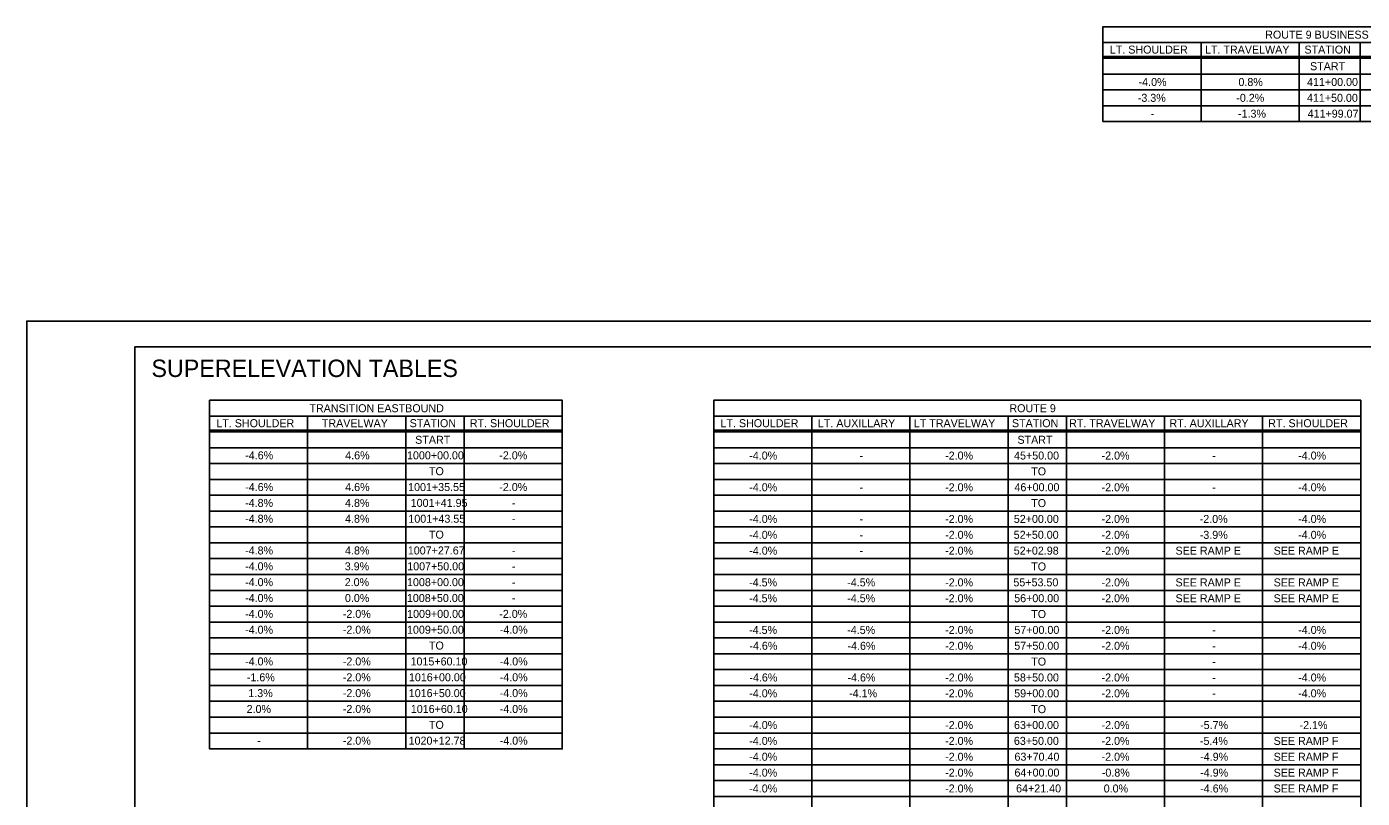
# Model space of a CAD drawing. Extents: x -15319374 to 1762012, y 465773 to 3693661.
# Drawn here: x -15317328 to -15316827, y 3691684 to 3691973 of the extents above; entities that cross this region are included whole.
import ezdxf

# ---------------------------------------------------------------- set-up
doc = ezdxf.new("R2010")
doc.units = 0
for name, color, linetype in [('BORDER', 7, 'Continuous'), ('DIMENSIONS', 7, 'Continuous'), ('PLOT BOUNDARY', 7, 'Continuous')]:
    doc.layers.add(name, color=color, linetype=linetype)

msp = doc.modelspace()

# ---------------------------------------------------------------- linework, layer by layer
at = {"layer": 'BORDER'}
for p, q in [((-15316887.84, 3691967.13), (-15316887.84, 3691937.48)), ((-15316851.07, 3691967.13), (-15316851.07, 3691937.48)), ((-15316828.2, 3691967.13), (-15316828.2, 3691937.48)), ((-15316924.61, 3691961.85), (-15316755.66, 3691961.85)), ((-15316924.61, 3691961.25), (-15316755.66, 3691961.25)), ((-15316924.61, 3691955.31), (-15316755.66, 3691955.31)), ((-15316924.61, 3691955.31), (-15316755.66, 3691955.31)), ((-15316924.61, 3691955.31), (-15316755.66, 3691955.31)), ((-15316924.61, 3691949.37), (-15316755.66, 3691949.37)), ((-15316924.61, 3691943.42), (-15316755.66, 3691943.42)), ((-15317259.46, 3691827.08), (-15317259.46, 3691708.88)), ((-15317222.69, 3691827.08), (-15317222.69, 3691702.35)), ((-15317185.92, 3691827.08), (-15317185.92, 3691702.35)), ((-15317164.05, 3691827.08), (-15317164.05, 3691702.35)), ((-15317070.51, 3691827.08), (-15317070.51, 3691482.47)), ((-15317033.74, 3691827.08), (-15317033.74, 3691482.47)), ((-15316996.97, 3691827.08), (-15316996.97, 3691482.47)), ((-15316960.21, 3691827.08), (-15316960.21, 3691482.47)), ((-15316938.33, 3691827.08), (-15316938.33, 3691482.47)), ((-15316901.56, 3691827.08), (-15316901.56, 3691482.47)), ((-15316864.8, 3691827.08), (-15316864.8, 3691482.47)), ((-15316828.03, 3691827.08), (-15316828.03, 3691482.47)), ((-15317259.46, 3691821.8), (-15317127.28, 3691821.8)), ((-15317259.46, 3691821.2), (-15317127.28, 3691821.2)), ((-15317033.74, 3691821.8), (-15317070.51, 3691821.8)), ((-15317033.74, 3691821.2), (-15317070.51, 3691821.2)), ((-15317070.51, 3691821.2), (-15317070.51, 3691482.47)), ((-15317033.74, 3691821.8), (-15316828.03, 3691821.8)), ((-15317033.74, 3691821.2), (-15316828.03, 3691821.2)), ((-15317259.46, 3691815.26), (-15317127.28, 3691815.26)), ((-15317259.46, 3691815.26), (-15317127.28, 3691815.26)), ((-15317259.46, 3691815.26), (-15317127.28, 3691815.26)), ((-15317070.51, 3691815.26), (-15316828.03, 3691815.26)), ((-15317070.51, 3691815.26), (-15316828.03, 3691815.26)), ((-15317070.51, 3691815.26), (-15316828.03, 3691815.26)), ((-15317259.46, 3691809.32), (-15317127.28, 3691809.32)), ((-15317070.51, 3691809.32), (-15316828.03, 3691809.32)), ((-15317259.46, 3691803.38), (-15317127.28, 3691803.38)), ((-15317070.51, 3691803.38), (-15316828.03, 3691803.38)), ((-15317259.46, 3691797.43), (-15317127.28, 3691797.43)), ((-15317070.51, 3691797.43), (-15316828.03, 3691797.43)), ((-15317259.46, 3691791.49), (-15317127.28, 3691791.49)), ((-15317070.51, 3691791.49), (-15316828.03, 3691791.49)), ((-15317259.46, 3691785.55), (-15317127.28, 3691785.55)), ((-15317070.51, 3691785.55), (-15316828.03, 3691785.55)), ((-15317259.46, 3691779.61), (-15317127.28, 3691779.61)), ((-15317070.51, 3691779.61), (-15316828.03, 3691779.61)), ((-15317259.46, 3691773.66), (-15317127.28, 3691773.66)), ((-15317070.51, 3691773.66), (-15316828.03, 3691773.66)), ((-15317259.46, 3691767.72), (-15317127.28, 3691767.72)), ((-15317070.51, 3691767.72), (-15316828.03, 3691767.72)), ((-15317259.46, 3691761.78), (-15317127.28, 3691761.78)), ((-15317070.51, 3691761.78), (-15316828.03, 3691761.78)), ((-15317259.46, 3691755.83), (-15317127.28, 3691755.83)), ((-15317070.51, 3691755.83), (-15316828.03, 3691755.83)), ((-15317259.46, 3691749.89), (-15317127.28, 3691749.89)), ((-15317070.51, 3691749.89), (-15316828.03, 3691749.89)), ((-15317259.46, 3691743.95), (-15317127.28, 3691743.95)), ((-15317070.51, 3691743.95), (-15316828.03, 3691743.95)), ((-15317259.46, 3691738.01), (-15317127.28, 3691738.01)), ((-15317070.51, 3691738.01), (-15316828.03, 3691738.01)), ((-15317259.46, 3691732.06), (-15317127.28, 3691732.06)), ((-15317070.51, 3691732.06), (-15316828.03, 3691732.06)), ((-15317259.46, 3691726.12), (-15317127.28, 3691726.12)), ((-15317070.51, 3691726.12), (-15316828.03, 3691726.12)), ((-15317259.46, 3691720.18), (-15317127.28, 3691720.18)), ((-15317070.51, 3691720.18), (-15316828.03, 3691720.18)), ((-15317259.46, 3691714.24), (-15317127.28, 3691714.24)), ((-15317070.51, 3691714.24), (-15316828.03, 3691714.24)), ((-15317259.46, 3691708.29), (-15317127.28, 3691708.29)), ((-15317070.51, 3691708.29), (-15316828.03, 3691708.29)), ((-15317259.46, 3691702.35), (-15317127.28, 3691702.35)), ((-15317070.51, 3691702.35), (-15316828.03, 3691702.35)), ((-15317070.51, 3691696.41), (-15316828.03, 3691696.41)), ((-15317070.51, 3691690.46), (-15316828.03, 3691690.46)), ((-15317070.51, 3691684.52), (-15316828.03, 3691684.52))]:
    msp.add_line(p, q, dxfattribs=at)
for points in [[(-15316924.61, 3691967.13), (-15316924.61, 3691973.07), (-15316755.66, 3691973.07), (-15316755.66, 3691967.13)], [(-15317259.46, 3691827.08), (-15317259.46, 3691833.02), (-15317127.28, 3691833.02), (-15317127.28, 3691827.08)], [(-15317033.74, 3691833.02), (-15317070.51, 3691833.02), (-15317070.51, 3691827.08)], [(-15317033.74, 3691833.02), (-15316864.8, 3691833.02)], [(-15316864.8, 3691833.02), (-15316828.03, 3691833.02), (-15316828.03, 3691827.08)]]:
    msp.add_lwpolyline(points, dxfattribs=at)
for points in [[(-15316924.61, 3691967.13), (-15316755.66, 3691967.13), (-15316755.66, 3691937.48), (-15316924.61, 3691937.48)], [(-15317287.5, 3691853.02), (-15316487.5, 3691853.02), (-15316487.5, 3691328.02), (-15317287.5, 3691328.02)], [(-15317259.46, 3691827.08), (-15317127.28, 3691827.08), (-15317127.28, 3691702.35), (-15317259.46, 3691702.35)], [(-15317070.51, 3691827.08), (-15316828.03, 3691827.08), (-15316828.03, 3691482.47), (-15317070.51, 3691482.47)]]:
    msp.add_lwpolyline(points, close=True, dxfattribs=at)
at = {"layer": 'PLOT BOUNDARY'}
msp.add_lwpolyline([(-15317327.97, 3691312.73), (-15316477.97, 3691312.73), (-15316477.97, 3691862.73), (-15317327.97, 3691862.73)], close=True, dxfattribs=at)

# ---------------------------------------------------------------- texts
at = {"layer": 'BORDER'}
msp.add_text('SUPERELEVATION TABLES', height=6.5214, rotation=360, dxfattribs=at).set_placement((-15317281.22, 3691841.76))
at = {"layer": 'DIMENSIONS'}
for s, p in [('ROUTE 9 BUSINESS', (-15316863.82, 3691968.6)), ('LT. SHOULDER', (-15316922.05, 3691962.99)), ('LT. TRAVELWAY', (-15316886.39, 3691962.99)), ('STATION', (-15316849.11, 3691962.99)), ('START', (-15316847.03, 3691956.76)), ('-4.0%', (-15316911.27, 3691950.85)), ('0.8%', (-15316873.85, 3691950.85)), ('411+00.00', (-15316848.13, 3691950.85)), ('-3.3%', (-15316911.56, 3691944.91)), ('-0.2%', (-15316874.65, 3691944.91)), ('411+50.00', (-15316848.18, 3691944.91)), ('-', (-15316906.73, 3691938.97)), ('-1.3%', (-15316874.01, 3691938.97)), ('411+99.07', (-15316847.92, 3691938.97)), ('TRANSITION EASTBOUND', (-15317222.01, 3691828.55)), ('ROUTE 9', (-15316959.68, 3691828.55)), ('LT. SHOULDER', (-15317256.9, 3691822.94)), ('TRAVELWAY', (-15317217.36, 3691822.94)), ('STATION', (-15317184.46, 3691822.94)), ('RT. SHOULDER', (-15317161.92, 3691822.94)), ('LT. SHOULDER', (-15317067.96, 3691822.94)), ('LT. AUXILLARY', (-15317031.46, 3691822.94)), ('LT TRAVELWAY', (-15316995.52, 3691822.94)), ('STATION', (-15316958.74, 3691822.94)), ('RT. TRAVELWAY', (-15316937.31, 3691822.94)), ('RT. AUXILLARY', (-15316899.71, 3691822.94)), ('RT. SHOULDER', (-15316862.67, 3691822.94)), ('START', (-15317182.38, 3691816.72)), ('START', (-15316956.67, 3691816.72)), ('-4.6%', (-15317246.08, 3691810.89)), ('4.6%', (-15317208.6, 3691810.89)), ('1000+00.00', (-15317185.44, 3691810.89)), ('-2.0%', (-15317150.86, 3691810.89)), ('-4.0%', (-15317057.18, 3691810.81)), ('-2.0%', (-15316983.78, 3691810.81)), ('45+50.00', (-15316957.93, 3691810.82)), ('-2.0%', (-15316925.14, 3691810.81)), ('-4.0%', (-15316851.46, 3691810.81)), ('-', (-15317015.87, 3691810.81)), ('-', (-15316883.69, 3691810.81)), ('TO', (-15317177.22, 3691804.95)), ('TO', (-15316951.51, 3691804.88)), ('-4.6%', (-15317246.08, 3691799)), ('4.6%', (-15317208.6, 3691799)), ('1001+35.55', (-15317185.03, 3691799)), ('-2.0%', (-15317150.86, 3691799)), ('-4.0%', (-15317057.18, 3691798.92)), ('-', (-15317015.87, 3691798.92)), ('-2.0%', (-15316983.78, 3691798.92)), ('46+00.00', (-15316957.79, 3691798.94)), ('-2.0%', (-15316925.14, 3691798.92)), ('-', (-15316883.69, 3691798.92)), ('-4.0%', (-15316851.46, 3691798.92)), ('-4.8%', (-15317246.12, 3691793.06)), ('4.8%', (-15317208.65, 3691793.06)), ('1001+41.95', (-15317184.06, 3691793.06)), ('-', (-15317146.17, 3691793.06)), ('TO', (-15316951.51, 3691792.99)), ('-4.8%', (-15317246.12, 3691787.12)), ('4.8%', (-15317208.65, 3691787.12)), ('1001+43.55', (-15317184.93, 3691787.12)), ('-', (-15317146.17, 3691787.12)), ('-4.0%', (-15317057.18, 3691787.04)), ('-', (-15317015.87, 3691787.04)), ('-2.0%', (-15316983.78, 3691787.04)), ('52+00.00', (-15316958.03, 3691787.05)), ('-2.0%', (-15316925.14, 3691787.04)), ('-2.0%', (-15316888.37, 3691787.04)), ('-4.0%', (-15316851.46, 3691787.04)), ('TO', (-15317177.22, 3691781.17)), ('-4.0%', (-15317057.18, 3691781.09)), ('-2.0%', (-15316983.78, 3691781.09)), ('52+50.00', (-15316958.08, 3691781.11)), ('-2.0%', (-15316925.14, 3691781.09)), ('-3.9%', (-15316888.35, 3691781.09)), ('-4.0%', (-15316851.46, 3691781.09)), ('-4.8%', (-15317246.12, 3691775.23)), ('4.8%', (-15317208.65, 3691775.23)), ('1007+27.67', (-15317185.14, 3691775.23)), ('-', (-15317015.87, 3691781.09)), ('52+02.98', (-15316958.06, 3691775.17)), ('-', (-15317146.17, 3691775.23)), ('-4.0%', (-15317057.18, 3691775.15)), ('-', (-15317015.87, 3691775.15)), ('-2.0%', (-15316983.78, 3691775.15)), ('-2.0%', (-15316925.14, 3691775.15)), ('SEE RAMP E', (-15316897.43, 3691775.15)), ('SEE RAMP E', (-15316860.66, 3691775.15)), ('-4.0%', (-15317246.12, 3691769.29)), ('3.9%', (-15317208.77, 3691769.29)), ('1007+50.00', (-15317185.37, 3691769.29)), ('-', (-15317146.17, 3691769.29)), ('TO', (-15316951.51, 3691769.22)), ('-4.0%', (-15317246.12, 3691763.35)), ('2.0%', (-15317208.79, 3691763.35)), ('1008+00.00', (-15317185.44, 3691763.35)), ('-', (-15317146.17, 3691763.35)), ('-4.5%', (-15317057.23, 3691763.26)), ('-4.5%', (-15317020.46, 3691763.26)), ('-2.0%', (-15316983.78, 3691763.26)), ('55+53.50', (-15316958.19, 3691763.28)), ('-2.0%', (-15316925.14, 3691763.26)), ('SEE RAMP E', (-15316897.43, 3691763.26)), ('SEE RAMP E', (-15316860.66, 3691763.26)), ('-4.0%', (-15317246.12, 3691757.4)), ('0.0%', (-15317208.7, 3691757.4)), ('1008+50.00', (-15317185.49, 3691757.4)), ('-', (-15317146.17, 3691757.4)), ('-4.5%', (-15317057.23, 3691757.32)), ('-4.5%', (-15317020.46, 3691757.32)), ('-2.0%', (-15316983.78, 3691757.32)), ('56+00.00', (-15316957.89, 3691757.34)), ('-2.0%', (-15316925.14, 3691757.32)), ('SEE RAMP E', (-15316897.43, 3691757.32)), ('SEE RAMP E', (-15316860.66, 3691757.32)), ('-4.0%', (-15317246.12, 3691751.46)), ('-2.0%', (-15317209.5, 3691751.46)), ('1009+00.00', (-15317185.4, 3691751.46)), ('-2.0%', (-15317150.86, 3691751.46)), ('TO', (-15316951.51, 3691751.4)), ('-4.0%', (-15317246.12, 3691745.52)), ('-2.0%', (-15317209.5, 3691745.52)), ('1009+50.00', (-15317185.44, 3691745.52)), ('-4.0%', (-15317150.71, 3691745.52)), ('-4.5%', (-15317057.23, 3691745.44)), ('-4.5%', (-15317020.46, 3691745.44)), ('-2.0%', (-15316983.78, 3691745.44)), ('57+00.00', (-15316957.82, 3691745.45)), ('-2.0%', (-15316925.14, 3691745.44)), ('-4.0%', (-15316851.46, 3691745.44)), ('-', (-15316883.69, 3691745.44)), ('TO', (-15317177.22, 3691739.58)), ('-4.6%', (-15317057.13, 3691739.49)), ('-4.6%', (-15317020.36, 3691739.49)), ('-2.0%', (-15316983.78, 3691739.49)), ('57+50.00', (-15316957.86, 3691739.51)), ('-2.0%', (-15316925.14, 3691739.49)), ('-', (-15316883.69, 3691739.49)), ('-4.0%', (-15316851.46, 3691739.49)), ('-4.0%', (-15317246.12, 3691733.63)), ('-2.0%', (-15317209.5, 3691733.63)), ('1015+60.10', (-15317184.12, 3691733.63)), ('-4.0%', (-15317150.71, 3691733.63)), ('TO', (-15316951.51, 3691733.57)), ('-', (-15316883.69, 3691733.55)), ('-1.6%', (-15317245.46, 3691727.69)), ('-2.0%', (-15317209.5, 3691727.69)), ('1016+00.00', (-15317184.73, 3691727.69)), ('-4.0%', (-15317150.71, 3691727.69)), ('-4.6%', (-15317057.13, 3691727.61)), ('-4.6%', (-15317020.36, 3691727.61)), ('-2.0%', (-15316983.78, 3691727.61)), ('58+50.00', (-15316957.98, 3691727.62)), ('-2.0%', (-15316925.14, 3691727.61)), ('-', (-15316883.69, 3691727.61)), ('-4.0%', (-15316851.46, 3691727.61)), ('1.3%', (-15317244.92, 3691721.75)), ('-2.0%', (-15317209.5, 3691721.75)), ('1016+50.00', (-15317184.78, 3691721.75)), ('-4.0%', (-15317150.71, 3691721.75)), ('-4.0%', (-15317057.18, 3691721.67)), ('-4.1%', (-15317019.75, 3691721.67)), ('-2.0%', (-15316983.78, 3691721.67)), ('59+00.00', (-15316957.89, 3691721.68)), ('-2.0%', (-15316925.14, 3691721.67)), ('-4.0%', (-15316851.46, 3691721.67)), ('2.0%', (-15317245.56, 3691715.81)), ('-2.0%', (-15317209.5, 3691715.81)), ('1016+60.10', (-15317184.02, 3691715.81)), ('-4.0%', (-15317150.71, 3691715.81)), ('TO', (-15316951.51, 3691715.74)), ('-', (-15316883.69, 3691721.67)), ('TO', (-15317177.22, 3691709.86)), ('-4.0%', (-15317057.18, 3691709.78)), ('-2.0%', (-15316983.78, 3691709.78)), ('63+00.00', (-15316957.96, 3691709.8)), ('-2.0%', (-15316925.14, 3691709.78)), ('-5.7%', (-15316888.21, 3691709.78)), ('-2.1%', (-15316850.94, 3691709.78)), ('-', (-15317241.58, 3691703.92)), ('-2.0%', (-15317209.5, 3691703.92)), ('1020+12.78', (-15317184.84, 3691703.92)), ('-4.0%', (-15317150.71, 3691703.92)), ('-4.0%', (-15317057.18, 3691703.84)), ('-2.0%', (-15316983.78, 3691703.84)), ('63+50.00', (-15316958, 3691703.85)), ('-2.0%', (-15316925.14, 3691703.84)), ('-5.4%', (-15316888.28, 3691703.84)), ('SEE RAMP F', (-15316860.66, 3691703.84)), ('-4.0%', (-15317057.18, 3691697.9)), ('-2.0%', (-15316983.78, 3691697.9)), ('63+70.40', (-15316957.79, 3691697.91)), ('-2.0%', (-15316925.14, 3691697.9)), ('-4.9%', (-15316888.18, 3691697.9)), ('SEE RAMP F', (-15316860.66, 3691697.9)), ('-4.0%', (-15317057.18, 3691691.95)), ('-2.0%', (-15316983.78, 3691691.95)), ('64+00.00', (-15316957.79, 3691691.97)), ('-0.8%', (-15316925.05, 3691691.95)), ('-4.9%', (-15316888.18, 3691691.95)), ('SEE RAMP F', (-15316860.66, 3691691.95)), ('-4.0%', (-15317057.18, 3691686.01)), ('-2.0%', (-15316983.78, 3691686.01)), ('64+21.40', (-15316957.18, 3691686.03)), ('0.0%', (-15316924.34, 3691686.01)), ('-4.6%', (-15316888.18, 3691686.01)), ('SEE RAMP F', (-15316860.66, 3691686.01))]:
    msp.add_text(s, height=3, dxfattribs=at).set_placement(p)

doc.saveas('drawing.dxf')
